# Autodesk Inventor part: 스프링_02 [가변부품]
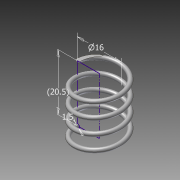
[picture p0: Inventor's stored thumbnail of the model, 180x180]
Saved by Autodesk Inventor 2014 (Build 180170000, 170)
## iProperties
Created: 2015-07
Part Number: 스프링_02 [가변부품]
Material: 강철, 연강
Document SubType Name: Modeling
Designer: Administrator
Density: 7.86 g/cm^3
Appearance: 강철
Mass: 2.74911 g
Surface Area: 9.46906 cm^2
Volume: 0.349759 cm^3
Author: Administrator
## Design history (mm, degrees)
sketch "스케치1"
  geometry: L1 (0, 0)-(8, 0); L2 (8, 0)-(8, 20.5); L3 (8, 20.5)-(0, 20.5); L4 (0, 20.5)-(0, 0); C1 r 0.75 at (8, 0)
  constraints: 8 end point, 2 parallel, 1 centre point, 1 coincident, 1 horizontal, 1 perpendicular
  dimensions: "d0" = 16 diameter of L2 L4; "d1" = 20.5 distance between parallel lines of L1 L3 (derived); "d2" = 1.5 diameter of C1
feature "코일1" sketch "스케치1" pitch "d3" = 10; turns "d5" = 4; dims "d4" = 20.5 (= d1), "d6" = 0, angle "d7" = 90 deg, angle "d8" = 90 deg, "d9" = 0, "d10" = 0
sketch "스케치2"
  geometry: L1 (-8.75, 0)-(-7.25, 0) reference; 1 further point
  constraints: 1 horizontal alignment
extrude "돌출1" cut sketch "스케치2" stored distance "d11" = 10; taper "d12" = 0 deg
node "작업 평면1"
sketch "스케치3"
  geometry: L1 (0.75, 0)-(-0.75, 0) reference; 1 further point
  constraints: 1 horizontal alignment
extrude "돌출2" cut sketch "스케치3" stored distance "d13" = 10; taper "d14" = 0 deg
node "솔리드1"
node "절단 모서리 투영1"
node "절단 모서리 투영2"
